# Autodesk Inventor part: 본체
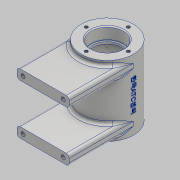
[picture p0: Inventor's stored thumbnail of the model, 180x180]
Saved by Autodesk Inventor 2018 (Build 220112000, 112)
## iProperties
Created: 2020-07
Part Number: 본체
Material: 알루미늄 6061
Document SubType Name: Modeling
Designer: home
Density: 2.7 g/cm^3
Appearance: 알루미늄 - 평지
Author: home
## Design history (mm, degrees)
sketch "스케치1"
  geometry: L1 (0, 0)-(0, -55.603); L2 (26, 7.199)-(17, 7.199); L3 (16, 6.199)-(16, -4.501); L4 (15.7, -4.801)-(14, -4.801); L5 (14, -4.801)-(14, -6.801); L6 (14, -6.801)-(18, -6.801); L7 (21, -9.801)-(21, -45.801); L8 (18, -48.801)-(14, -48.801); L9 (14, -48.801)-(14, -50.801); L10 (14, -50.801)-(15.7, -50.801); L11 (16, -51.101)-(16, -61.801); L12 (17, -62.801)-(26, -62.801); L13 (26, -62.801)-(26, 7.199); L14 (16, 6.199)-(17, 7.199); L15 (16, -61.801)-(17, -62.801); A1 r 0.3 centre (15.7, -4.501) between (15.7, -4.801) and (16, -4.501); A2 r 0.3 centre (15.7, -51.101) between (16, -51.101) and (15.7, -50.801); A3 r 3 centre (18, -45.801) between (18, -48.801) and (21, -45.801); A4 r 3 centre (18, -9.801) between (21, -9.801) and (18, -6.801); 8 further points
  constraints: 30 end point, 16 point on line, 9 perpendicular, 8 point on circle, 8 tangent, 4 centre point, 2 equal radius, 2 midpoint, 1 horizontal, 1 horizontal alignment, 1 vertical
  dimensions: "d0" = 32 diameter of L3 L1; "d1" = 28 diameter of L5 L1; "d3" = 52 diameter of L13 L1; "d5" = 12 distance of point (16, 7.199) point (16, -4.801); "d6" = 12 distance of point (16, -50.801) point (16, -62.801); "d7" = 2 distance of L4.end L5.end; "d8" = 2 distance of L8.end L9.end; "d10" = 42 distance of point (21, -6.801) point (21, -48.801); "d11" = 42 diameter of L7 L1; "d12" = 7.19866 distance from line of L1.start L2; "d13" = 0.3 radius of A1; "d14" = 3 radius of A3; "d15" = 1 distance of L3.start point (16, 7.199); "d16" = 45 deg angle of L3 L14; "d17" = 1 distance of L11.end point (16, -62.801) (= d15); "d18" = 45 deg angle of L11 L15 (= d16)
revolve "회전1" sketch "스케치1" stored, may be unused: angle "d19" = 90 deg
sketch "스케치2"
  geometry: 1 further point
node "작업 평면1"
sketch "스케치3"
  geometry: L1 (-26, 7.199)-(26, 7.199) reference; C1 r 5 at (0, -27.801); 1 further point
  constraints: 1 centre point
  dimensions: "d21" = 10 diameter of C1; "d22" = 35 distance from line of L1 C1.centre; "d23" = 26 horizontal distance of L1.start C1.centre
extrude "돌출1" join sketch "스케치3" stored distance "d24" = 10; taper "d25" = 0 deg; dims "d0" = 32, "d1" = 28, "d3" = 52, "d5" = 12, "d6" = 12, "d7" = 2, "d8" = 2, "d10" = 42, "d11" = 42, "d12" = 7.19866, "d13" = 0.3, "d14" = 3, "d15" = 1, "d16" = 45 deg, "d17" = 1 (= d15), "d18" = 45 deg (= d16)
node "작업 평면3"
  node "작업 평면2"
sketch "스케치4"
  geometry: L1 (26, 0)-(26, -64); L2 (26, -64)-(-26, -64); L3 (-26, -64)-(-26, 0); A1 r 26 centre (0, 0) between (26, 0) and (-26, 0) reference; 1 further point
  constraints: 6 end point, 2 perpendicular, 2 point on circle, 1 tangent, 1 vertical
  dimensions: "d27" = 52 distance of L1.end L2.end; "d28" = 64 distance of L1.start L1.end
extrude "돌출2" join sketch "스케치4" distance "d29" = 10; taper "d30" = 0 deg
node "작업 평면4"
sketch "스케치5"
  geometry: L1 (0, 0)-(9.919, -27.251); L2 (0, 0)-(0, -45.606); 1 further point
  constraints: 4 end point, 1 coincident, 1 vertical
  dimensions: "d31" = 20 deg angle of L2 L1; "d32" = 29 distance of L1.start L1.end; "d33" = 15.59812 distance from line of L2.end L1
node "작업 평면5"
sketch "스케치7"
  geometry: C1 r 26 at (0, 0) reference; 2 further points
  constraints: 1 vertical alignment
  dimensions: "d38" = 21 distance of point (0, 21) point (0, 0)
hole "구멍1" sketch "스케치7" at (0, 21) diameter "d39" = 3.242; stored, may be unused: countersink angle "d43" = 90 deg, drill point angle "d45" = 118 deg; dims "d40" = 8, "d41" = 4, "d42" = 2, "d44" = 10
sketch "스케치8"
  geometry: C1 r 5 at (0, 0) reference; 2 further points
  constraints: 1 coincident
hole "구멍2" sketch "스케치8" at (0, 0) diameter "d49" = 5.188; stored, may be unused: countersink angle "d53" = 90 deg, drill point angle "d55" = 0 deg; dims "d50" = 12, "d51" = 4, "d52" = 2, "d54" = 16
sketch "스케치10"
  geometry: L1 (0, 10)-(52, 10) reference; L2 (0, -50)-(52, -50) reference; 5 further points
  constraints: 2 horizontal alignment, 2 vertical alignment
  dimensions: "d63" = 5 distance from line of L1 point (46, 5); "d64" = 40 distance of point (6, 5) point (46, 5); "d65" = 20 horizontal distance of point (26, 7.801) point (46, 5); "d66" = 5 distance from line of L2 point (46, -45)
hole "구멍4" sketch "스케치10" at (46, 5), (46, -45), (6, -45), (6, 5) diameter "d67" = 4.134; stored, may be unused: countersink angle "d71" = 90 deg, drill point angle "d73" = 118 deg; dims "d68" = 8, "d69" = 4, "d70" = 2, "d72" = 10
fillet "모깎기1" dims "d74" = 3
fillet "모깎기2" dims "d75" = 3, "d76" = 2
node "작업 평면6"
sketch "스케치11"
  geometry: L1 (-26, 7.199)-(26, 7.199) reference; L2 (26, 7.199)-(26, -62.801) reference; 2 further points
  constraints: 1 other
  dimensions: "d78" = 35 distance from line of L1 point (0, -27.801); "d79" = 26 distance from line of L2 point (0, -27.801)
feature "엠보싱1" sketch "스케치11" dims "d80" = 0.5, "d81" = 0
node "작업 평면7"
sketch "스케치12"
  geometry: L1 (0, 0)-(-9.919, -27.251); L2 (0, 0)-(0, -49.376); 1 further point
  constraints: 4 end point, 1 coincident, 1 vertical
  dimensions: "d82" = 20 deg angle of L2 L1; "d83" = 29 distance of L1.start L1.end; "d84" = 16.88773 distance from line of L2.end L1
node "작업 평면9"
sketch "스케치14"
  geometry: L1 (24.432, -27)-(46.321, -27) reference; C1 r 6 at (0, 0); 1 further point
  constraints: 1 centre point
  dimensions: "d85" = 12 diameter of C1; "d86" = 27.80134 distance of point (0, 27.801) C1.centre; "d87" = 27 distance from line of L1 C1.centre
extrude "돌출4" join sketch "스케치14" stored distance "d88" = 10; taper "d89" = 0 deg
sketch "스케치15"
  geometry: C1 r 6 at (0, 0) reference; 2 further points
  constraints: 1 coincident
hole "구멍5" sketch "스케치15" at (0, 0) diameter "d90" = 5.188; stored, may be unused: countersink angle "d94" = 90 deg, drill point angle "d96" = 0 deg; dims "d91" = 12, "d92" = 4, "d93" = 2, "d95" = 16
fillet "모깎기3" dims "d97" = 2
node "솔리드1"
mirror "미러1"
pattern_circular "원형 패턴1" dims angle "d47" = 360 deg
mirror "미러2"
node "투영된 루프2"
other parameters: "d20" = 29, "d77" = 48
